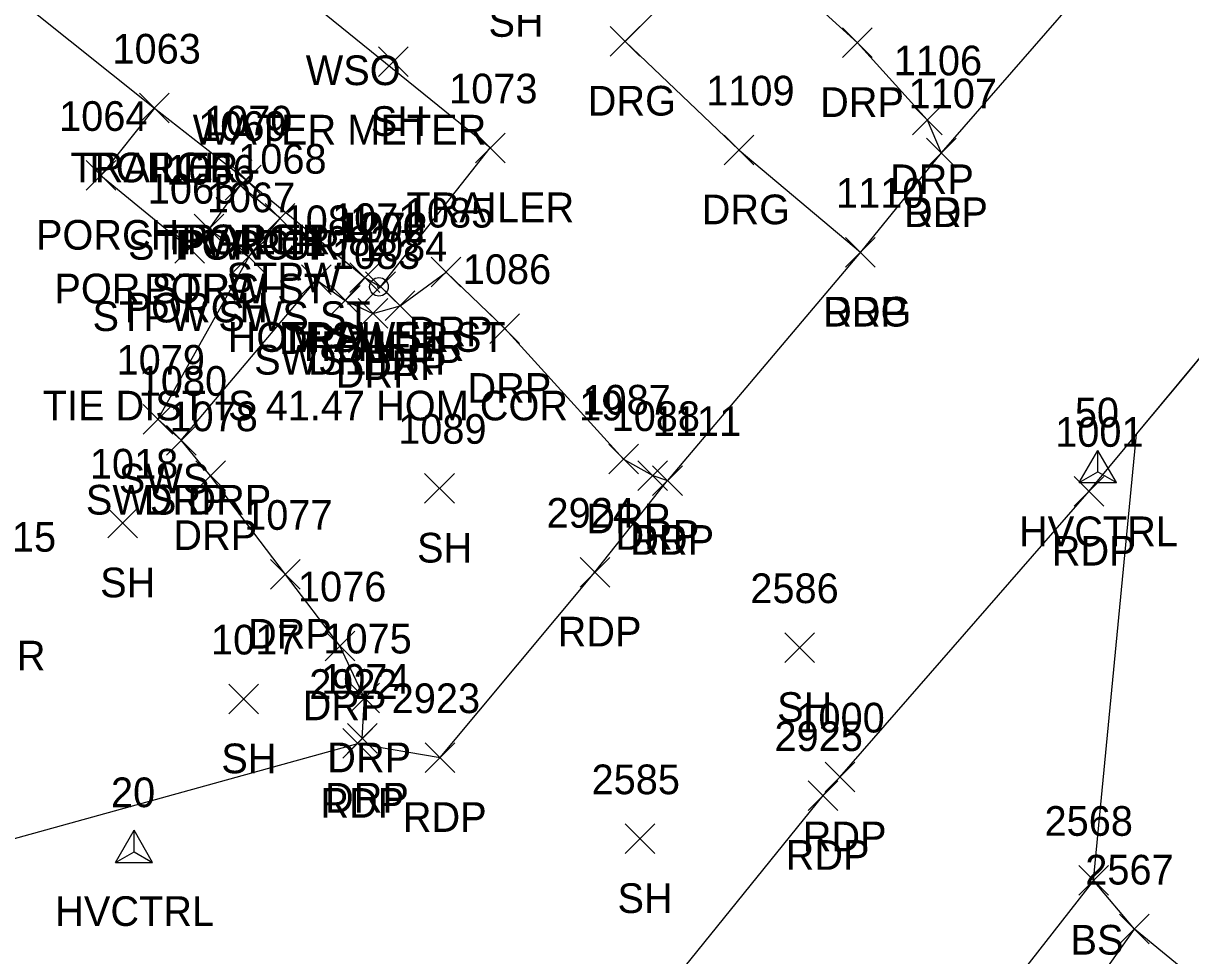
# Model space of a CAD drawing. Extents: x 1638344 to 1639591, y 610835 to 612202.
# Drawn here: x 1638801.1 to 1638879.7, y 611706.8 to 611769.6 of the extents above; entities that cross this region are included whole.
import ezdxf

# ---------------------------------------------------------------- set-up
doc = ezdxf.new("R2010")
doc.units = 0
for name, color, linetype in [('C_A', 7, 'Continuous'), ('C_C', 7, 'Continuous'), ('C_I', 7, 'Continuous'), ('CBP', 7, 'Continuous'), ('CPSM', 7, 'Continuous'), ('L_A', 7, 'Continuous'), ('L_I', 7, 'Continuous'), ('L_TIC', 7, 'Continuous'), ('LBC', 7, 'Continuous'), ('LBF', 7, 'Continuous'), ('LELB', 7, 'Continuous'), ('LSOGP', 7, 'Continuous'), ('P_A', 7, 'Continuous'), ('P_I', 7, 'Continuous'), ('P_TIC', 7, 'Continuous'), ('PET', 7, 'Continuous'), ('R_A', 7, 'Continuous'), ('R_I', 7, 'Continuous'), ('R_TIC', 7, 'Continuous'), ('RDG', 7, 'Continuous'), ('RDP', 7, 'Continuous'), ('RSW', 7, 'Continuous'), ('U_A', 7, 'Continuous'), ('U_C', 7, 'Continuous')]:
    doc.layers.add(name, color=color, linetype=linetype)

msp = doc.modelspace()

# ---------------------------------------------------------------- linework, layer by layer
at = {"layer": 'CBP'}
for radius in [0.625, 0.0833]:
    msp.add_circle((1638825.087, 611751.848), radius, dxfattribs=at)
at = {"layer": 'CPSM'}
for p, q in [((1638872.238, 611738.656), (1638873.488, 611740.821)), ((1638872.238, 611738.656), (1638873.488, 611740.821)), ((1638874.738, 611738.656), (1638873.488, 611740.821)), ((1638873.488, 611739.377), (1638873.488, 611740.821)), ((1638874.738, 611738.656), (1638873.488, 611740.821)), ((1638873.488, 611739.377), (1638873.488, 611740.821)), ((1638872.238, 611738.656), (1638873.488, 611739.377)), ((1638872.238, 611738.656), (1638873.488, 611739.377)), ((1638873.488, 611739.377), (1638873.488, 611739.377)), ((1638873.488, 611739.377), (1638874.738, 611738.656)), ((1638873.488, 611739.377), (1638873.488, 611739.377)), ((1638873.488, 611739.377), (1638874.738, 611738.656)), ((1638872.238, 611738.656), (1638874.738, 611738.656)), ((1638872.238, 611738.656), (1638874.738, 611738.656)), ((1638807.348, 611713.078), (1638808.598, 611715.243)), ((1638807.348, 611713.078), (1638808.598, 611715.243)), ((1638807.348, 611713.078), (1638808.598, 611715.243)), ((1638807.348, 611713.078), (1638808.598, 611715.243)), ((1638807.348, 611713.078), (1638808.598, 611715.243)), ((1638807.348, 611713.078), (1638808.598, 611715.243)), ((1638807.348, 611713.078), (1638808.598, 611715.243)), ((1638807.348, 611713.078), (1638808.598, 611715.243)), ((1638807.348, 611713.078), (1638808.598, 611715.243)), ((1638807.348, 611713.078), (1638808.598, 611715.243)), ((1638807.348, 611713.078), (1638808.598, 611715.243)), ((1638807.348, 611713.078), (1638808.598, 611715.243)), ((1638809.848, 611713.078), (1638808.598, 611715.243)), ((1638808.598, 611713.799), (1638808.598, 611715.243)), ((1638809.848, 611713.078), (1638808.598, 611715.243)), ((1638808.598, 611713.799), (1638808.598, 611715.243)), ((1638809.848, 611713.078), (1638808.598, 611715.243)), ((1638808.598, 611713.799), (1638808.598, 611715.243)), ((1638809.848, 611713.078), (1638808.598, 611715.243)), ((1638808.598, 611713.799), (1638808.598, 611715.243)), ((1638809.848, 611713.078), (1638808.598, 611715.243)), ((1638808.598, 611713.799), (1638808.598, 611715.243)), ((1638809.848, 611713.078), (1638808.598, 611715.243)), ((1638808.598, 611713.799), (1638808.598, 611715.243)), ((1638809.848, 611713.078), (1638808.598, 611715.243)), ((1638808.598, 611713.799), (1638808.598, 611715.243)), ((1638809.848, 611713.078), (1638808.598, 611715.243)), ((1638808.598, 611713.799), (1638808.598, 611715.243)), ((1638809.848, 611713.078), (1638808.598, 611715.243)), ((1638808.598, 611713.799), (1638808.598, 611715.243)), ((1638809.848, 611713.078), (1638808.598, 611715.243)), ((1638808.598, 611713.799), (1638808.598, 611715.243)), ((1638809.848, 611713.078), (1638808.598, 611715.243)), ((1638808.598, 611713.799), (1638808.598, 611715.243)), ((1638809.848, 611713.078), (1638808.598, 611715.243)), ((1638808.598, 611713.799), (1638808.598, 611715.243)), ((1638807.348, 611713.078), (1638808.598, 611713.799)), ((1638807.348, 611713.078), (1638808.598, 611713.799)), ((1638807.348, 611713.078), (1638808.598, 611713.799)), ((1638807.348, 611713.078), (1638808.598, 611713.799)), ((1638807.348, 611713.078), (1638808.598, 611713.799)), ((1638807.348, 611713.078), (1638808.598, 611713.799)), ((1638807.348, 611713.078), (1638808.598, 611713.799)), ((1638807.348, 611713.078), (1638808.598, 611713.799)), ((1638807.348, 611713.078), (1638808.598, 611713.799)), ((1638807.348, 611713.078), (1638808.598, 611713.799)), ((1638807.348, 611713.078), (1638808.598, 611713.799)), ((1638807.348, 611713.078), (1638808.598, 611713.799)), ((1638807.348, 611713.078), (1638809.848, 611713.078)), ((1638807.348, 611713.078), (1638809.848, 611713.078)), ((1638807.348, 611713.078), (1638809.848, 611713.078)), ((1638807.348, 611713.078), (1638809.848, 611713.078)), ((1638807.348, 611713.078), (1638809.848, 611713.078)), ((1638807.348, 611713.078), (1638809.848, 611713.078)), ((1638807.348, 611713.078), (1638809.848, 611713.078)), ((1638807.348, 611713.078), (1638809.848, 611713.078)), ((1638807.348, 611713.078), (1638809.848, 611713.078)), ((1638807.348, 611713.078), (1638809.848, 611713.078)), ((1638807.348, 611713.078), (1638809.848, 611713.078)), ((1638807.348, 611713.078), (1638809.848, 611713.078)), ((1638808.598, 611713.799), (1638808.598, 611713.799)), ((1638808.598, 611713.799), (1638809.848, 611713.078)), ((1638808.598, 611713.799), (1638808.598, 611713.799)), ((1638808.598, 611713.799), (1638809.848, 611713.078)), ((1638808.598, 611713.799), (1638808.598, 611713.799)), ((1638808.598, 611713.799), (1638809.848, 611713.078)), ((1638808.598, 611713.799), (1638808.598, 611713.799)), ((1638808.598, 611713.799), (1638809.848, 611713.078)), ((1638808.598, 611713.799), (1638808.598, 611713.799)), ((1638808.598, 611713.799), (1638809.848, 611713.078)), ((1638808.598, 611713.799), (1638808.598, 611713.799)), ((1638808.598, 611713.799), (1638809.848, 611713.078)), ((1638808.598, 611713.799), (1638808.598, 611713.799)), ((1638808.598, 611713.799), (1638809.848, 611713.078)), ((1638808.598, 611713.799), (1638808.598, 611713.799)), ((1638808.598, 611713.799), (1638809.848, 611713.078)), ((1638808.598, 611713.799), (1638808.598, 611713.799)), ((1638808.598, 611713.799), (1638809.848, 611713.078)), ((1638808.598, 611713.799), (1638808.598, 611713.799)), ((1638808.598, 611713.799), (1638809.848, 611713.078)), ((1638808.598, 611713.799), (1638808.598, 611713.799)), ((1638808.598, 611713.799), (1638809.848, 611713.078)), ((1638808.598, 611713.799), (1638808.598, 611713.799)), ((1638808.598, 611713.799), (1638809.848, 611713.078))]:
    msp.add_line(p, q, dxfattribs=at)
at = {"layer": 'L_TIC'}
for points in [[(1638825.05, 611766.009), (1638827.05, 611768.009)], [(1638827.05, 611766.009), (1638825.05, 611768.009)], [(1638808.966, 611762.882), (1638810.966, 611764.882)], [(1638810.966, 611762.882), (1638808.966, 611764.882)], [(1638808.966, 611762.882), (1638810.966, 611764.882)], [(1638810.966, 611762.882), (1638808.966, 611764.882)], [(1638831.585, 611760.2), (1638833.585, 611762.2)], [(1638833.585, 611760.2), (1638831.585, 611762.2)], [(1638805.372, 611758.348), (1638807.372, 611760.348)], [(1638807.372, 611758.348), (1638805.372, 611760.348)], [(1638814.743, 611757.672), (1638816.743, 611759.672)], [(1638816.743, 611757.672), (1638814.743, 611759.672)], [(1638814.743, 611757.672), (1638816.743, 611759.672)], [(1638816.743, 611757.672), (1638814.743, 611759.672)], [(1638815.167, 611758.038), (1638817.167, 611760.038)], [(1638817.167, 611758.038), (1638815.167, 611760.038)], [(1638815.167, 611758.038), (1638817.167, 611760.038)], [(1638817.167, 611758.038), (1638815.167, 611760.038)], [(1638817.43, 611755.467), (1638819.43, 611757.467)], [(1638819.43, 611755.467), (1638817.43, 611757.467)], [(1638812.654, 611754.733), (1638814.654, 611756.733)], [(1638814.654, 611754.733), (1638812.654, 611756.733)], [(1638812.654, 611754.733), (1638814.654, 611756.733)], [(1638814.654, 611754.733), (1638812.654, 611756.733)], [(1638811.342, 611753.447), (1638813.342, 611755.447)], [(1638813.342, 611753.447), (1638811.342, 611755.447)], [(1638815.318, 611752.87), (1638817.318, 611754.87)], [(1638817.318, 611752.87), (1638815.318, 611754.87)], [(1638823.136, 611751.467), (1638825.136, 611753.467)], [(1638825.136, 611751.467), (1638823.136, 611753.467)], [(1638824.192, 611750.85), (1638826.192, 611752.85)], [(1638826.192, 611750.85), (1638824.192, 611752.85)], [(1638828.163, 611737.276), (1638830.163, 611739.276)], [(1638830.163, 611737.276), (1638828.163, 611739.276)], [(1638806.829, 611734.933), (1638808.829, 611736.933)], [(1638808.829, 611734.933), (1638806.829, 611736.933)], [(1638852.405, 611726.543), (1638854.405, 611728.543)], [(1638854.405, 611726.543), (1638852.405, 611728.543)], [(1638814.986, 611723.084), (1638816.986, 611725.084)], [(1638816.986, 611723.084), (1638814.986, 611725.084)], [(1638841.661, 611713.672), (1638843.661, 611715.672)], [(1638843.661, 611713.672), (1638841.661, 611715.672)], [(1638872.205, 611710.87), (1638874.205, 611712.87)], [(1638874.205, 611710.87), (1638872.205, 611712.87)], [(1638874.948, 611707.59), (1638876.948, 611709.59)], [(1638876.948, 611707.59), (1638874.948, 611709.59)]]:
    msp.add_lwpolyline(points, dxfattribs=at)
at = {"layer": 'LBC'}
msp.add_lwpolyline([(1638778.535, 611789.972), (1638779.981, 611788.141), (1638780.108, 611787.933), (1638790.106, 611779.828), (1638792.8, 611777.592), (1638809.966, 611763.882), (1638816.167, 611759.038), (1638824.136, 611752.467), (1638825.192, 611751.85), (1638832.585, 611761.2), (1638787.915, 611797.359), (1638787.153, 611796.949), (1638785.81, 611798.58)], dxfattribs=at)
at = {"layer": 'LBF'}
for points in [[(1638809.966, 611763.882), (1638806.372, 611759.348), (1638812.342, 611754.447), (1638813.654, 611755.733), (1638815.743, 611758.672), (1638816.167, 611759.038)], [(1638813.654, 611755.733), (1638816.318, 611753.87), (1638818.43, 611756.467), (1638815.743, 611758.672)]]:
    msp.add_lwpolyline(points, dxfattribs=at)
at = {"layer": 'LELB'}
for points in [[(1638873.205, 611711.87), (1638857.7, 611692.044), (1638852.155, 611680.328), (1638857.497, 611671.464), (1638870.873, 611660.135), (1638883.737, 611648.029), (1638891.391, 611642.842)], [(1638893.271, 611644.216), (1638875.108, 611664.315), (1638860.571, 611677.054), (1638859.029, 611684.692), (1638875.948, 611708.59)]]:
    msp.add_lwpolyline(points, dxfattribs=at)
at = {"layer": 'LSOGP'}
msp.add_lwpolyline([(1638890.128, 611696.929), (1638875.948, 611708.59), (1638873.205, 611711.87), (1638876.094, 611741.92), (1638879.29, 611745.769), (1638882.486, 611749.617)], dxfattribs=at)
at = {"layer": 'P_TIC'}
for points in [[(1638861.949, 611759.869), (1638863.949, 611761.869)], [(1638863.949, 611759.869), (1638861.949, 611761.869)], [(1638856.502, 611753.171), (1638858.502, 611755.171)], [(1638858.502, 611753.171), (1638856.502, 611755.171)], [(1638843.514, 611737.798), (1638845.514, 611739.798)], [(1638845.514, 611737.798), (1638843.514, 611739.798)], [(1638871.898, 611737.072), (1638873.898, 611739.072)], [(1638873.898, 611737.072), (1638871.898, 611739.072)], [(1638838.629, 611731.622), (1638840.629, 611733.622)], [(1638840.629, 611731.622), (1638838.629, 611733.622)], [(1638822.655, 611720.09), (1638824.655, 611722.09)], [(1638824.655, 611720.09), (1638822.655, 611722.09)], [(1638828.206, 611719.135), (1638830.206, 611721.135)], [(1638830.206, 611719.135), (1638828.206, 611721.135)], [(1638855.127, 611717.83), (1638857.127, 611719.83)], [(1638857.127, 611717.83), (1638855.127, 611719.83)], [(1638853.977, 611716.582), (1638855.977, 611718.582)], [(1638855.977, 611716.582), (1638853.977, 611718.582)]]:
    msp.add_lwpolyline(points, dxfattribs=at)
at = {"layer": 'PET'}
for points in [[(1638882.098, 611783.043), (1638878.664, 611778.943), (1638862.949, 611760.869), (1638857.502, 611754.171), (1638844.514, 611738.798)], [(1638856.127, 611718.83), (1638872.898, 611738.072), (1638898.466, 611768.86)], [(1638839.629, 611732.622), (1638844.514, 611738.798)], [(1638777.651, 611708.363), (1638823.655, 611721.09), (1638829.206, 611720.135), (1638839.629, 611732.622)], [(1638854.977, 611717.582), (1638856.127, 611718.83)], [(1638854.977, 611717.582), (1638835.394, 611693.37), (1638831.854, 611686.651), (1638832.562, 611684.206)]]:
    msp.add_lwpolyline(points, dxfattribs=at)
at = {"layer": 'R_TIC'}
for points in [[(1638840.655, 611767.379), (1638842.655, 611769.379)], [(1638842.655, 611767.379), (1638840.655, 611769.379)], [(1638856.3, 611767.286), (1638858.3, 611769.286)], [(1638858.3, 611767.286), (1638856.3, 611769.286)], [(1638861.004, 611762.09), (1638863.004, 611764.09)], [(1638863.004, 611762.09), (1638861.004, 611764.09)], [(1638848.331, 611760.06), (1638850.331, 611762.06)], [(1638850.331, 611760.06), (1638848.331, 611762.06)], [(1638861.949, 611759.869), (1638863.949, 611761.869)], [(1638863.949, 611759.869), (1638861.949, 611761.869)], [(1638815.318, 611752.87), (1638817.318, 611754.87)], [(1638817.318, 611752.87), (1638815.318, 611754.87)], [(1638856.502, 611753.171), (1638858.502, 611755.171)], [(1638858.502, 611753.171), (1638856.502, 611755.171)], [(1638819.874, 611751.326), (1638821.874, 611753.326)], [(1638821.874, 611751.326), (1638819.874, 611753.326)], [(1638823.136, 611751.467), (1638825.136, 611753.467)], [(1638825.136, 611751.467), (1638823.136, 611753.467)], [(1638828.602, 611751.837), (1638830.602, 611753.837)], [(1638830.602, 611751.837), (1638828.602, 611753.837)], [(1638821.821, 611749.933), (1638823.821, 611751.933)], [(1638823.821, 611749.933), (1638821.821, 611751.933)], [(1638821.821, 611749.933), (1638823.821, 611751.933)], [(1638823.821, 611749.933), (1638821.821, 611751.933)], [(1638825.511, 611749.567), (1638827.511, 611751.567)], [(1638827.511, 611749.567), (1638825.511, 611751.567)], [(1638823.684, 611749.051), (1638825.684, 611751.051)], [(1638825.684, 611749.051), (1638823.684, 611751.051)], [(1638832.557, 611748.034), (1638834.557, 611750.034)], [(1638834.557, 611748.034), (1638832.557, 611750.034)], [(1638809.203, 611741.929), (1638811.203, 611743.929)], [(1638811.203, 611741.929), (1638809.203, 611743.929)], [(1638810.774, 611740.507), (1638812.774, 611742.507)], [(1638812.774, 611740.507), (1638810.774, 611742.507)], [(1638810.774, 611740.507), (1638812.774, 611742.507)], [(1638812.774, 611740.507), (1638810.774, 611742.507)], [(1638840.558, 611739.241), (1638842.558, 611741.241)], [(1638842.558, 611739.241), (1638840.558, 611741.241)], [(1638812.758, 611738.122), (1638814.758, 611740.122)], [(1638814.758, 611738.122), (1638812.758, 611740.122)], [(1638842.522, 611738.133), (1638844.522, 611740.133)], [(1638844.522, 611738.133), (1638842.522, 611740.133)], [(1638843.514, 611737.798), (1638845.514, 611739.798)], [(1638845.514, 611737.798), (1638843.514, 611739.798)], [(1638817.786, 611731.479), (1638819.786, 611733.479)], [(1638819.786, 611731.479), (1638817.786, 611733.479)], [(1638821.462, 611726.655), (1638823.462, 611728.655)], [(1638823.462, 611726.655), (1638821.462, 611728.655)], [(1638823.118, 611723.151), (1638825.118, 611725.151)], [(1638825.118, 611723.151), (1638823.118, 611725.151)], [(1638822.968, 611720.436), (1638824.968, 611722.436)], [(1638824.968, 611720.436), (1638822.968, 611722.436)]]:
    msp.add_lwpolyline(points, dxfattribs=at)
at = {"layer": 'RDG'}
msp.add_lwpolyline([(1638849.073, 611775.784), (1638841.655, 611768.379), (1638849.331, 611761.06), (1638857.502, 611754.171)], dxfattribs=at)
at = {"layer": 'RDP'}
for points in [[(1638878.664, 611778.943), (1638876.178, 611779.904), (1638870.649, 611784.567), (1638865.023, 611778.459), (1638863.627, 611778.059), (1638854.783, 611784.128), (1638848.747, 611776.419), (1638849.073, 611775.784), (1638857.3, 611768.286), (1638862.004, 611763.09), (1638862.949, 611760.869)], [(1638823.968, 611721.436), (1638824.118, 611724.151), (1638822.462, 611727.655), (1638818.786, 611732.479), (1638813.758, 611739.122), (1638811.774, 611741.507), (1638820.874, 611752.326), (1638822.821, 611750.933), (1638824.684, 611750.051), (1638826.511, 611750.567), (1638829.602, 611752.837), (1638833.557, 611749.034), (1638841.558, 611740.241), (1638843.522, 611739.133), (1638844.514, 611738.798)]]:
    msp.add_lwpolyline(points, dxfattribs=at)
at = {"layer": 'RSW'}
for points in [[(1638816.318, 611753.87), (1638810.203, 611742.929), (1638811.774, 611741.507)], [(1638824.136, 611752.467), (1638822.821, 611750.933)]]:
    msp.add_lwpolyline(points, dxfattribs=at)

# ---------------------------------------------------------------- texts
at = {"layer": 'C_A'}
for s, p in [('TIE', (1638823.166, 611746.848)), ('HVCTRL', (1638868.181, 611734.377)), ('HVCTRL', (1638868.181, 611734.377)), ('HVCTRL', (1638803.291, 611708.799)), ('HVCTRL', (1638803.291, 611708.799)), ('HVCTRL', (1638803.291, 611708.799)), ('HVCTRL', (1638803.291, 611708.799)), ('HVCTRL', (1638803.291, 611708.799)), ('HVCTRL', (1638803.291, 611708.799)), ('HVCTRL', (1638803.291, 611708.799)), ('HVCTRL', (1638803.291, 611708.799)), ('HVCTRL', (1638803.291, 611708.799)), ('HVCTRL', (1638803.291, 611708.799)), ('HVCTRL', (1638803.291, 611708.799)), ('HVCTRL', (1638803.291, 611708.799))]:
    msp.add_text(s, height=2, dxfattribs=at).set_placement(p)
at = {"layer": 'C_C'}
msp.add_text('TIE DIST IS 41.47 HOM COR 19', height=2, dxfattribs=at).set_placement((1638802.45, 611742.848))
at = {"layer": 'C_I'}
for s, p in [('1200', (1638822.229, 611754.848)), ('50', (1638871.937, 611742.377)), ('50', (1638871.937, 611742.377)), ('20', (1638807.047, 611716.799)), ('20', (1638807.047, 611716.799)), ('20', (1638807.047, 611716.799)), ('20', (1638807.047, 611716.799)), ('20', (1638807.047, 611716.799)), ('20', (1638807.047, 611716.799)), ('20', (1638807.047, 611716.799)), ('20', (1638807.047, 611716.799)), ('20', (1638807.047, 611716.799)), ('20', (1638807.047, 611716.799)), ('20', (1638807.047, 611716.799)), ('20', (1638807.047, 611716.799))]:
    msp.add_text(s, height=2, dxfattribs=at).set_placement(p)
at = {"layer": 'L_A'}
for s, p in [('SH', (1638832.464, 611768.686)), ('SH', (1638824.538, 611762.009)), ('TRAILER', (1638804.32, 611758.882)), ('PORCH', (1638805.588, 611758.882)), ('TRAILER', (1638826.939, 611756.2)), ('PORCH', (1638801.994, 611754.348)), ('STPW POR', (1638808.192, 611753.672)), ('TRAILER', (1638810.521, 611754.038)), ('PORCH', (1638811.365, 611753.672)), ('PORCH', (1638811.789, 611754.038)), ('STPW', (1638814.823, 611751.467)), ('POR STPW ST', (1638803.237, 611750.733)), ('PORCH', (1638809.276, 611750.733)), ('STPW SWS ST', (1638805.806, 611748.87)), ('PORCH', (1638807.964, 611749.447)), ('TRAILER', (1638818.49, 611747.467)), ('TRAILER', (1638819.547, 611746.85)), ('SH', (1638827.651, 611733.276)), ('SH', (1638806.318, 611730.933)), ('FNR', (1638797.143, 611726.008)), ('SH', (1638851.893, 611722.543)), ('SH', (1638814.474, 611719.084)), ('SH', (1638841.149, 611709.672)), ('BS', (1638871.646, 611706.87))]:
    msp.add_text(s, height=2, dxfattribs=at).set_placement(p)
at = {"layer": 'L_I'}
for s, p in [('1063', (1638807.147, 611766.882)), ('1063', (1638807.147, 611766.882)), ('1073', (1638829.813, 611764.2)), ('1064', (1638803.554, 611762.348)), ('1069', (1638812.916, 611761.672)), ('1069', (1638812.916, 611761.672)), ('1070', (1638813.309, 611762.038)), ('1070', (1638813.309, 611762.038)), ('1068', (1638815.611, 611759.467)), ('1066', (1638810.78, 611758.733)), ('1066', (1638810.78, 611758.733)), ('1065', (1638809.523, 611757.447)), ('1067', (1638813.499, 611756.87)), ('1071', (1638821.931, 611755.467)), ('1072', (1638822.421, 611754.85)), ('1089', (1638826.383, 611741.276)), ('1018', (1638805.625, 611738.933)), ('1015', (1638797.403, 611734.008)), ('2586', (1638850.09, 611730.543)), ('1017', (1638813.781, 611727.084)), ('2585', (1638839.401, 611717.672)), ('2568', (1638869.898, 611714.87)), ('2567', (1638872.641, 611711.59))]:
    msp.add_text(s, height=2, dxfattribs=at).set_placement(p)
at = {"layer": 'P_A'}
for p in [(1638860.438, 611755.869), (1638854.99, 611749.171), (1638842.003, 611733.798), (1638870.386, 611733.072), (1638837.117, 611727.622), (1638821.143, 611716.09), (1638826.694, 611715.135), (1638853.615, 611713.83), (1638852.465, 611712.582)]:
    msp.add_text('RDP', height=2, dxfattribs=at).set_placement(p)
at = {"layer": 'P_I'}
for s, p in [('1107', (1638860.745, 611763.869)), ('1110', (1638855.856, 611757.171)), ('1111', (1638843.522, 611741.798)), ('1001', (1638870.614, 611741.072)), ('2924', (1638836.369, 611735.622)), ('2922', (1638820.395, 611724.09)), ('2923', (1638825.946, 611723.135)), ('1000', (1638853.19, 611721.83)), ('2925', (1638851.717, 611720.582))]:
    msp.add_text(s, height=2, dxfattribs=at).set_placement(p)
at = {"layer": 'R_A'}
for s, p in [('DRG', (1638839.143, 611763.379)), ('DRP', (1638854.788, 611763.286)), ('DRP', (1638859.492, 611758.09)), ('DRG', (1638846.819, 611756.06)), ('DRP', (1638860.438, 611755.869)), ('STPW SWS ST', (1638805.806, 611748.87)), ('DRG', (1638854.99, 611749.171)), ('HOM SWS1 ST', (1638814.9, 611747.467)), ('DRP', (1638818.363, 611747.326)), ('DRP', (1638827.09, 611747.837)), ('SWS1 DRP', (1638816.688, 611745.933)), ('DRP', (1638820.31, 611745.933)), ('DRP', (1638822.172, 611745.051)), ('DRP', (1638823.999, 611745.567)), ('DRP', (1638831.045, 611744.034)), ('SWS', (1638807.573, 611737.929)), ('SWS DRP', (1638805.357, 611736.507)), ('DRP', (1638809.262, 611736.507)), ('DRP', (1638839.046, 611735.241)), ('DRP', (1638811.246, 611734.122)), ('DRP', (1638841.01, 611734.133)), ('DRP', (1638842.003, 611733.798)), ('DRP', (1638816.274, 611727.479)), ('DRP', (1638819.95, 611722.655)), ('DRP', (1638821.606, 611719.151)), ('DRP', (1638821.457, 611716.436))]:
    msp.add_text(s, height=2, dxfattribs=at).set_placement(p)
at = {"layer": 'R_I'}
for s, p in [('1106', (1638859.744, 611766.09)), ('1109', (1638847.119, 611764.06)), ('1107', (1638860.745, 611763.869)), ('1067', (1638813.499, 611756.87)), ('1110', (1638855.856, 611757.171)), ('1085', (1638826.83, 611755.837)), ('1081', (1638818.67, 611755.326)), ('1071', (1638821.931, 611755.467)), ('1082', (1638820.05, 611753.933)), ('1082', (1638820.05, 611753.933)), ('1084', (1638823.74, 611753.567)), ('1083', (1638821.912, 611753.051)), ('1086', (1638830.73, 611752.034)), ('1079', (1638807.423, 611745.929)), ('1080', (1638808.916, 611744.507)), ('1080', (1638808.916, 611744.507)), ('1087', (1638838.786, 611743.241)), ('1078', (1638810.986, 611742.122)), ('1088', (1638840.75, 611742.133)), ('1111', (1638843.522, 611741.798)), ('1077', (1638816.014, 611735.479)), ('1076', (1638819.635, 611730.655)), ('1075', (1638821.347, 611727.151)), ('1074', (1638821.197, 611724.436))]:
    msp.add_text(s, height=2, dxfattribs=at).set_placement(p)
at = {"layer": 'U_A'}
msp.add_text('WSO', height=2, dxfattribs=at).set_placement((1638820.16, 611765.43))
at = {"layer": 'U_C'}
msp.add_text('WATER METER', height=2, dxfattribs=at).set_placement((1638812.553, 611761.43))

doc.saveas('drawing.dxf')
